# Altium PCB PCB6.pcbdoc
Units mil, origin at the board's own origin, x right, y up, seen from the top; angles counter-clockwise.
Board outline 1190 x 1010 mil, 2 copper layers (Top Layer, Bottom Layer), stack 62.206 mil thick; 18 components, 19 nets, 67 pads, 57 vias.
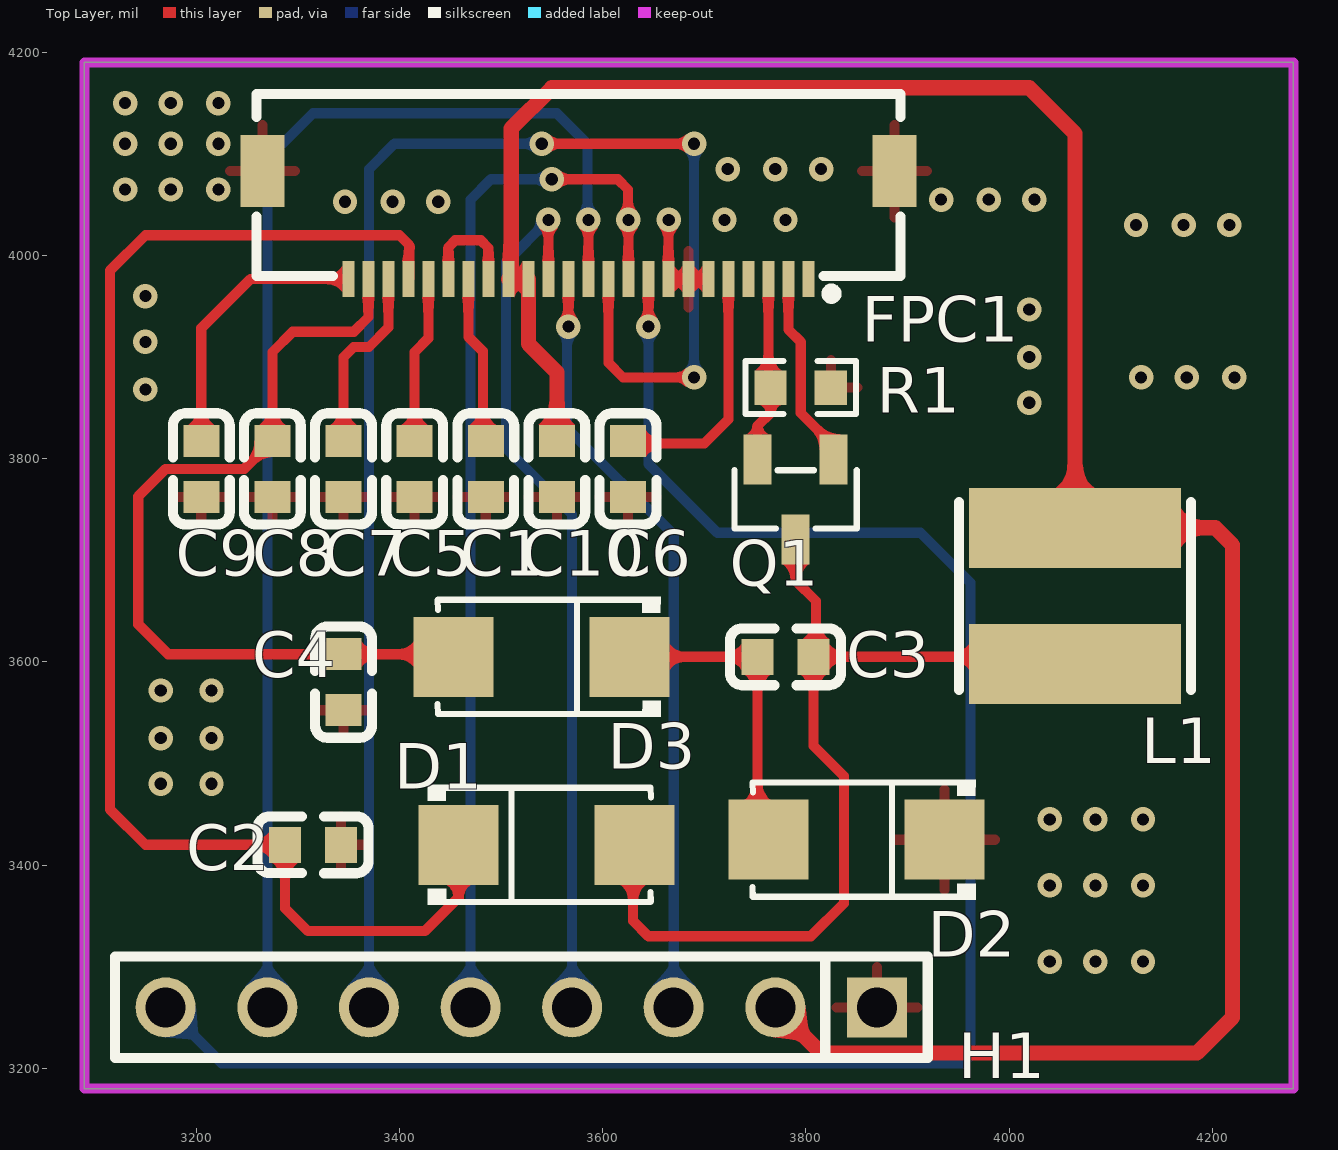
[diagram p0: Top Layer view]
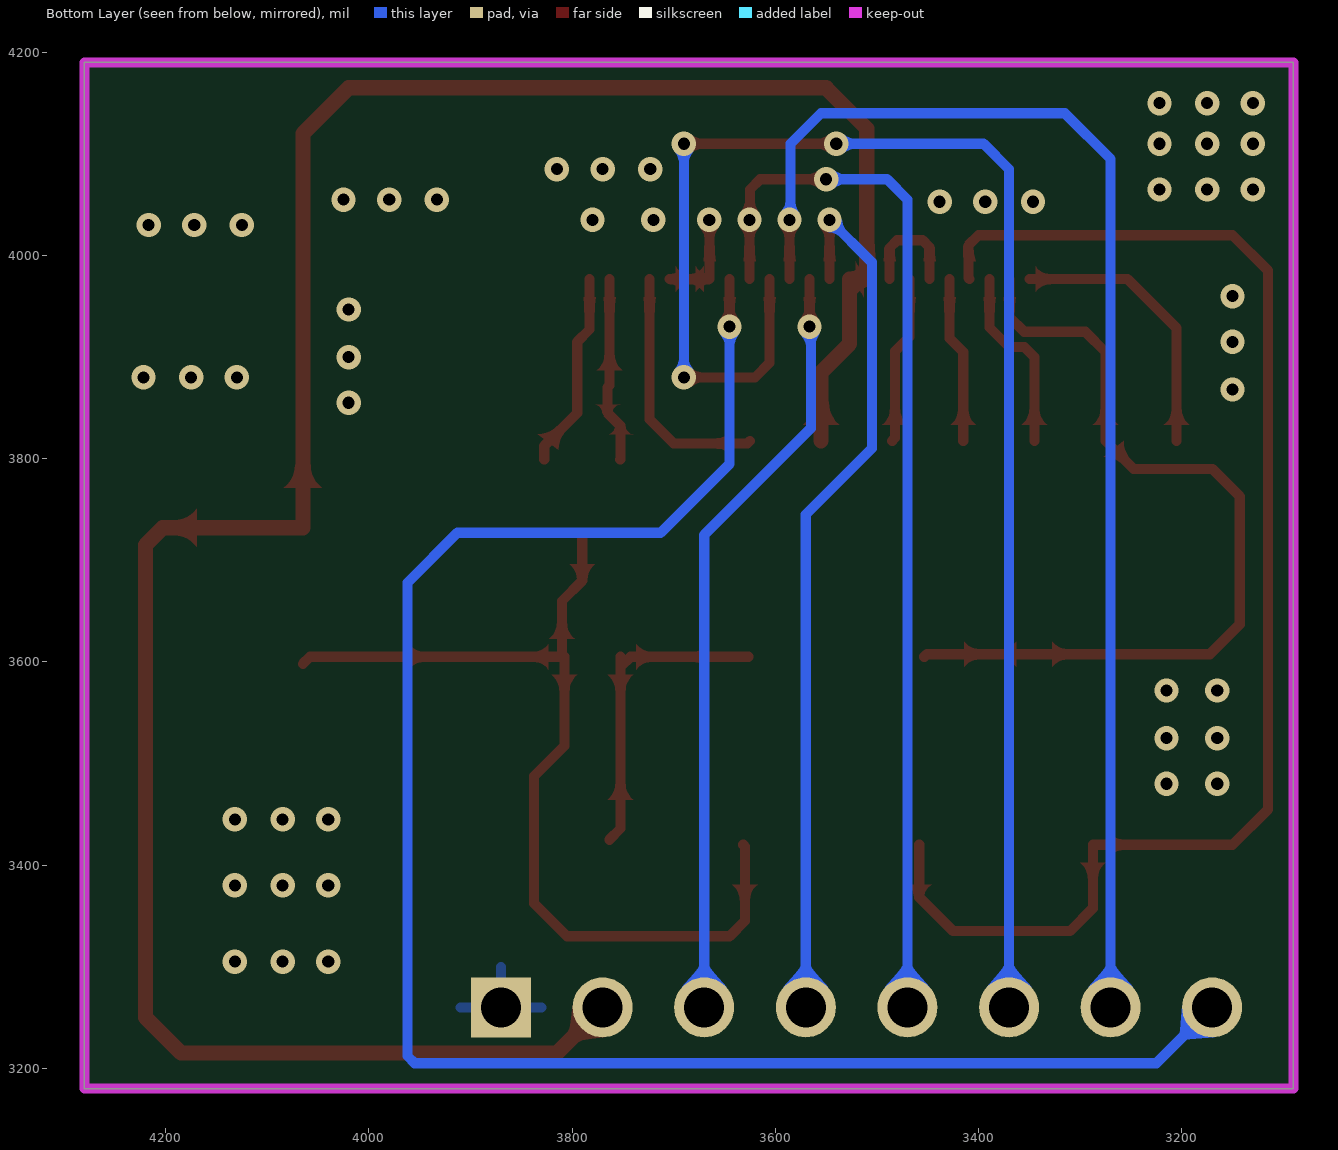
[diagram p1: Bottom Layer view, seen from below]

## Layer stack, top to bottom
Top Solder Mask Layer: solder mask 0.394, Dk 3.3
Top Layer: signal copper 1.379
Dielectric1: surface 59.449, FR4, Dk 4.5
Bottom Layer: signal copper 1.378
Bottom Solder Mask Layer: solder mask 0.394, Dk 3.3

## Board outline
3090,4190 4280,4190 4280,3180 3090,3180

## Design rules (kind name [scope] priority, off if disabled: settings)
BoardOutlineClearance copperThickness1oz [All] p0: genericclearance=10 ignorepadtopadclearanceinfootprint=FALSE except(0: Arc-SplitContinuation Track-SplitContinuation SMDPad-SplitContinuation THPad-SplitContinuation Via-SplitContinuation Fill-SplitContinuation Poly-SplitContinuation Region-SplitContinuation Text-SplitContinuation)
BoardOutlineClearance copperThickness2oz [All] p0: genericclearance=10 ignorepadtopadclearanceinfootprint=FALSE except(0: Arc-SplitContinuation Track-SplitContinuation SMDPad-SplitContinuation THPad-SplitContinuation Via-SplitContinuation Fill-SplitContinuation Poly-SplitContinuation Region-SplitContinuation Text-SplitContinuation)
BoardOutlineClearance otherClearance [All] p0: genericclearance=10 ignorepadtopadclearanceinfootprint=FALSE except(0: Arc-SplitContinuation Track-SplitContinuation SMDPad-SplitContinuation THPad-SplitContinuation Via-SplitContinuation Fill-SplitContinuation Poly-SplitContinuation Region-SplitContinuation Text-SplitContinuation)
Clearance copperThickness1oz [All] p1: gap=7 ignorepadtopadclearanceinfootprint=FALSE
Clearance copperThickness2oz [All] p1: gap=7 ignorepadtopadclearanceinfootprint=FALSE
Clearance otherClearance [All] p1: gap=7 ignorepadtopadclearanceinfootprint=FALSE
DiffPairsRouting differentialPair [All] p1: maxuncoupledlength=10 minlimit=6 maxlimit=Infinity mostfreqgap=6 toplayer_minwidth=5 toplayer_prefwidth=10 toplayer_maxwidth=100 bottomlayer_minwidth=5 bottomlayer_prefwidth=10 bottomlayer_maxwidth=100
PasteMaskExpansion pasteMaskExpansion [All] p1: expansion=0
PlaneConnect innerPlane [All] p1: planeconnectstyle=Relief reliefexpansion=20 reliefentries=4 reliefconductorwidth=10 reliefairgap=10
PolygonConnect copperRegion [All] p1: connectstyle=Relief reliefentries=4 reliefconductorwidth=10 polygonreliefangle="90 Angle" airgapwidth=10
RoutingVias viaSize [All] p1: viastyle="Through Hole" holewidth=12.0078 minholewidth=11.811 maxholewidth=248.0314 width=12.0078 minwidth=11.811 maxwidth=248.0314
SolderMaskExpansion solderMaskExpansion [IsVia] p1: useseparateexpansions=TRUE expansion=-1000 expansionbottom=-1000
SolderMaskExpansion solderMaskExpansion [All] p2: useseparateexpansions=TRUE expansion=2 expansionbottom=2
Width copperThickness1oz [All] p1: maxlimit=100 minlimit=5 preferedwidth=10
Width copperThickness2oz [All] p1: maxlimit=100 minlimit=8 preferedwidth=10

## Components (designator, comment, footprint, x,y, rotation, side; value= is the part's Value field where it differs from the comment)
C1 "1uF" C0603 3485,3790 r90 top
C2 "1uF" C0603 3315,3420 r0 top
C3 "1uF" C0603 3780,3605 r180 top
C4 "1uF" C0603 3345,3580 r270 top
C5 "1uF" C0603 3415,3790 r90 top
C6 "1uF" C0603 3625,3790 r90 top
C7 "1uF" C0603 3345,3790 r90 top
C8 "1uF" C0603 3275,3790 r90 top
C9 "1uF" C0603 3205,3790 r90 top
C10 "1uF" C0603 3555,3790 r90 top
D1 "SS14" SMA_L4.3-W2.6-LS5.2-RD 3545,3420 r0 top
D2 "SS14" SMA_L4.3-W2.6-LS5.2-RD 3850,3425 r180 top
D3 "SS14" SMA_L4.3-W2.6-LS5.2-RD 3540,3605 r180 top
FPC1 "FPC24-T1T1-2021-A" FPC-SMD_FPC24-T1T1-2021-A 3576.18,4029.87 r180 top
H1 "PZ254V-11-08P" HDR-TH_8P-P2.54-V-M 3520,3260 r180 top
L1 "47uH" IND-SMD_L4.7-W4.7_YPRH4D28 4065,3665 r90 top
Q1 "AO3400A" SOT-23-3_L2.9-W1.3-P1.90-LS2.4-BR 3790,3760 r90 top
R1 "2.2Ω" R0603 3795,3870 r180 top

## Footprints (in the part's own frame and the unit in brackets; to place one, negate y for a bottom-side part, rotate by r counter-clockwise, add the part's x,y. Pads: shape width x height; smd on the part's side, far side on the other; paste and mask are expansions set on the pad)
C0603 [mm]
  rect 0.8x0.9 smd: 1(-0.7,0) 2(0.7,0)
  silkscreen extent -1.39,-0.71 1.39,0.71
FPC-SMD_FPC24-T1T1-2021-A [mm]
  rect 0.3x0.9 smd paste+0 mask+0.05: 1(-5.75,1.35) 2(-5.25,1.35) 3(-4.75,1.35) 4(-4.25,1.35) 5(-3.75,1.35) 6(-3.25,1.35) 7(-2.75,1.35) 8(-2.25,1.35) 9(-1.75,1.35) 10(-1.25,1.35) 11(-0.75,1.35) 12(-0.25,1.35) 13(0.25,1.35) 14(0.75,1.35) 15(1.25,1.35) 16(1.75,1.35) 17(2.25,1.35) 18(2.75,1.35) 19(3.25,1.35) 20(3.75,1.35) 21(4.25,1.35) 22(4.75,1.35) 23(5.25,1.35) 24(5.75,1.35)
  rect 1.1x1.8 smd paste+0 mask+0.05: 25(7.9,-1.35) 26(-7.9,-1.35)
  silkscreen extent -8.05,-3.28 8.05,1.84
HDR-TH_8P-P2.54-V-M [mm]
  rect 1.5x1.5 hole 1: 1(-8.89,0)
  round 1.5 hole 1: 2(-6.35,0) 3(-3.81,0) 4(-1.27,0) 5(1.27,0) 6(3.81,0) 7(6.35,0) 8(8.89,0)
  silkscreen extent -10.16,-1.27 10.16,1.27
IND-SMD_L4.7-W4.7_YPRH4D28 [mm]
  rect 2x5.3 smd: 1(-1.7,0) 2(1.7,0)
  silkscreen extent -2.35,-2.9 2.35,2.9
R0603 [mil]
  rect 31.75x34.02 smd paste-3937.01 mask+2: 1(-29.66,0) 2(29.66,0)
  silkscreen extent -55,-26 55,26
SMA_L4.3-W2.6-LS5.2-RD [mm]
  rect 2x2 smd: 1(-2.2,0) 2(2.2,0)
  silkscreen extent -2.98,-1.5 2.6,1.5
SOT-23-3_L2.9-W1.3-P1.90-LS2.4-BR [mm]
  rect 1.25x0.7 smd: 1(1,-0.95) 2(1,0.95) 3(-1,0)
  silkscreen extent -0.73,-1.53 0.73,1.53

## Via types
v1: diameter 24.02, hole 12.01, Top Layer to Bottom Layer, 57 vias

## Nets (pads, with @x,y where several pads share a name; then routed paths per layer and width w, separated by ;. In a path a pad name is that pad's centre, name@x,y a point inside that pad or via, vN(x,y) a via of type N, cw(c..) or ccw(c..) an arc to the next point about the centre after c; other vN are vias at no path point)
$1N32: C3.2 D2.2 D3.1 | length 314.5
  Top Layer w10: D3.1 3742.44,3605 C3.2@3752.44,3595 ; C3.2 C3.2@3752.44,3595 ; D2.2 3752.44,3435.95 C3.2@3752.44,3595
$1N34: C3.1 D1.2 L1.1 Q1.3 | length 943
  Top Layer w10: D1.2 3630,3418.39 3630,3345 3645,3330 3805,3330 3837.5,3362.5 3837.5,3487.5 3807.56,3517.44 C3.1 ; Q1.3 3790,3680 3810,3660 3810,3607.44 C3.1 ; L1.1 4058.07,3605 C3.1
+3V3: C10.2 FPC1.15 FPC1.16 H1.2 L1.2 | length 2428.3
  Top Layer w15: C10.2 3555,3885 3526.97,3913.03 FPC1.15 FPC1.16 3510,3979.44 3510,4125 3550,4165 4020,4165 4065,4120 L1.2 4203.07,3731.93 4220,3715 4220,3250 4185,3215 3815,3215 H1.2
BUSY: FPC1.9 H1.8 | length 1831
  Top Layer w10: v1(3645.08,3930) FPC1.9
  Bottom Layer w10: H1.8 3225,3205 3955,3205 3962.07,3212.07 3962.07,3677.93 3912.93,3727.07 3712.93,3727.07 3645,3795 3645,3929.92 v1(3645.08,3930)
CS: FPC1.12 H1.7 | length 1314.8
  Top Layer w10: FPC1.12 v1(3586.02,4035)
  Bottom Layer w10: H1.7 3270,4095 3315,4140 3555,4140 3585,4110 3585,4036.02 v1(3586.02,4035)
D/C: FPC1.11 H1.6 | length 1558
  Top Layer w10: v1(3540,4110) v1(3690,4110) ; FPC1.11 3605.71,3894.29 3620,3880 v1(3690,3880)
  Bottom Layer w10: H1.6 3370,4085 3395,4110 v1(3540,4110) ; v1(3690,3880) v1(3690,4110)
GDR: FPC1.2 Q1.1 | length 195.8
  Top Layer w10: FPC1.2 3782.87,3927.13 3795,3915 3795,3845 3827.4,3812.6 Q1.1
GND: C1.1 C2.2 C4.2 C5.1 C6.1 C7.1 C8.1 C9.1 C10.1 D2.1 FPC1.6 FPC1.7 FPC1.8 FPC1.17 FPC1.19 FPC1.25 FPC1.26 H1.1 R1.1 | length 205.3
  Top Layer w10: FPC1.19 3448.23,4008.23 3455,4015 3480,4015 3487.6,4007.4 FPC1.17 ; v1(3665,4035) 3664.76,4034.76 FPC1.8 FPC1.7 FPC1.6
  other v1: 4040,3305 4085,3305 4131.88,3305 4040,3380 4085,3380 4131.88,3380 4040,3445 4085,3445 4131.88,3445 3165,3480 3215,3480 3165,3525 3215,3525 3165,3571.88 3215,3571.88 4020,3855 3150,3868.12 4130,3880 4175,3880 4221.88,3880 4020,3900 3150,3915 4020,3946.88 3150,3960 4125,4030 4171.88,4030 4216.88,4030 3720,4035 3780,4035 3346.43,4052.95 3393.31,4052.95 3438.31,4052.95 3933.12,4055 3980,4055 4025,4055 3130,4065 3175,4065 3221.88,4065 3723.12,4085 3770,4085 3815,4085 3130,4110 3175,4110 3221.88,4110 3130,4150 3175,4150 3221.88,4150
RES: FPC1.10 H1.5 | length 1050.9
  Top Layer w10: v1(3550,4075) 3615,4075 3625,4065 3625,4035.39 v1(3625.39,4035) FPC1.10
  Bottom Layer w10: H1.5 3470,4055 3490,4075 v1(3550,4075)
RESE: FPC1.3 Q1.2 R1.2 | length 183.6
  Top Layer w10: Q1.2 3752.5,3799.47 3752.5,3832.5 3765.34,3845.34 R1.2 3763.19,3872.15 FPC1.3
SCL: FPC1.13 H1.3 | length 760.8
  Top Layer w10: v1(3566.34,3930) FPC1.13
  Bottom Layer w10: v1(3566.34,3930) 3565,3928.66 3565,3830 3670,3725 H1.3
SDA: FPC1.14 H1.4 | length 877.5
  Top Layer w10: FPC1.14 v1(3546.65,4035)
  Bottom Layer w10: v1(3546.65,4035) 3505,3993.35 3505,3810 3570,3745 H1.4
VCOM: C9.2 FPC1.24 | length 275.7
  Top Layer w10: C9.2 3205,3928.45 3253.28,3976.72 FPC1.24
VDD: C1.2 FPC1.18 | length 166.2
  Top Layer w10: FPC1.18 3467.91,3920 3482.18,3905.73 3482.18,3820.38 C1.2
VGH: C2.1 D1.1 FPC1.21 | length 1372.5
  Top Layer w10: FPC1.21 3410,3977.86 3410,4010 3400,4020 3150,4020 3115,3985 3115,3455 3150,3420 C2.1 3287.44,3357.56 3310,3335 3425,3335 3458.39,3368.39 D1.1
VGL: C4.1 C8.2 D3.2 FPC1.23 | length 837.8
  Top Layer w10: FPC1.23 3369.49,3939.49 3355,3925 3295,3925 3275,3905 C8.2 3247.44,3790 3170,3790 3142.93,3762.93 3142.93,3637.07 3172.44,3607.56 C4.1 3450.83,3607.56 D3.2
VSH1: C5.2 FPC1.20 | length 164.8
  Top Layer w10: C5.2 3415,3905 3428.54,3918.54 FPC1.20
VSH2: C6.2 FPC1.5 | length 247.7
  Top Layer w10: C6.2 3627.56,3815 3700,3815 3723.82,3838.82 FPC1.5
VSL: C7.2 FPC1.22 | length 186.2
  Top Layer w10: C7.2 3345,3900 3355,3910 3370,3910 3389.17,3929.17 FPC1.22
pads on no net: FPC1.1 FPC1.4

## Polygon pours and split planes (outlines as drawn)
GND on Top Layer (solid, remove dead copper, pour order 0): 3045,4245 4380,4245 4380,3065 3045,3065
GND on Bottom Layer (solid, remove dead copper, pour order 4): 3000,4305 4490,4305 4490,3000 3000,3000

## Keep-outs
Board Outline Layer:
  the board outline again, w10

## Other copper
Top Layer:
  region net VCOM: 3328.9,3971.72 3328.9,3981.72 ccw(c3328.9,4000.47) 3343.9,3989.22 3343.9,3964.22 ccw(c3328.9,3952.97)
  region net VCOM: 3200,3848.31 3210,3848.31 ccw(c3228.75,3848.31) 3217.5,3833.31 3192.5,3833.31 ccw(c3181.25,3848.31)
  region net VSL: 3394.17,3944.01 3384.17,3944.01 ccw(c3259.48,3944.01) 3383.27,3959.01 3395.08,3959.01 ccw(c3518.87,3944.01)
  region net VSL: 3340,3848.31 3350,3848.31 ccw(c3368.75,3848.31) 3357.5,3833.31 3332.5,3833.31 ccw(c3321.25,3848.31)
  region net VSH1: 3433.54,3944.01 3423.54,3944.01 ccw(c3298.85,3944.01) 3422.64,3959.01 3434.45,3959.01 ccw(c3558.24,3944.01)
  region net VSH1: 3410,3848.31 3420,3848.31 ccw(c3438.75,3848.31) 3427.5,3833.31 3402.5,3833.31 ccw(c3391.25,3848.31)
  region net VGL: 3270,3848.31 3280,3848.31 ccw(c3298.75,3848.31) 3287.5,3833.31 3262.5,3833.31 ccw(c3251.25,3848.31)
  region net VGL: 3374.49,3944.01 3364.49,3944.01 ccw(c3239.8,3944.01) 3363.59,3959.01 3375.4,3959.01 ccw(c3499.19,3944.01)
  region net VDD: 3472.91,3944.01 3462.91,3944.01 ccw(c3338.22,3944.01) 3462.01,3959.01 3473.82,3959.01 ccw(c3597.61,3944.01)
  region net VDD: 3477.18,3848.31 3487.18,3848.31 ccw(c3505.93,3848.31) 3494.68,3833.31 3469.68,3833.31 ccw(c3458.43,3848.31)
  region net RESE: 3768.19,3944.01 3758.19,3944.01 ccw(c3633.5,3944.01) 3757.29,3959.01 3769.1,3959.01 ccw(c3892.89,3944.01)
  region net RESE: 3758.19,3902.01 3768.19,3902.01 ccw(c3786.94,3902.01) 3775.69,3887.01 3750.69,3887.01 ccw(c3739.44,3902.01)
  region net RESE: 3770.34,3845.34 3760.34,3845.34 ccw(c3752.69,3845.34) 3752.84,3852.99 3777.84,3852.99 ccw(c3777.99,3845.34)
  region net RESE: 3747.5,3832.5 3757.5,3832.5 ccw(c3766.09,3832.5) 3765,3823.98 3740,3823.98 ccw(c3738.91,3832.5)
  region net GDR: 3787.87,3944.01 3777.87,3944.01 ccw(c3653.18,3944.01) 3776.97,3959.01 3788.78,3959.01 ccw(c3912.57,3944.01)
  region net GDR: 3808.32,3824.61 3817.79,3829.28 ccw(c3833.7,3850.49) 3833.7,3823.98 3813.62,3808.7 ccw(c3787.1,3808.7)
  region net $1N32: 3680.98,3610 3680.98,3600 ccw(c3680.98,3581.25) 3665.98,3592.5 3665.98,3617.5 ccw(c3680.98,3628.75)
  region net $1N32: 3721.69,3600 3721.69,3610 ccw(c3721.69,3628.75) 3736.69,3617.5 3736.69,3592.5 ccw(c3721.69,3581.25)
  region net $1N34: 3838.31,3610 3838.31,3600 ccw(c3838.31,3581.25) 3823.31,3592.5 3823.31,3617.5 ccw(c3838.31,3628.75)
  region net $1N34: 3945.67,3600 3945.67,3610 ccw(c3945.67,3628.75) 3960.67,3617.5 3960.67,3592.5 ccw(c3945.67,3581.25)
  region net $1N34: 3795,3681.02 3785,3681.02 ccw(c3766.25,3681.02) 3777.5,3696.02 3802.5,3696.02 ccw(c3813.75,3681.02)
  region net $1N34: 3805,3637.72 3815,3637.72 ccw(c3833.75,3637.72) 3822.5,3622.72 3797.5,3622.72 ccw(c3786.25,3637.72)
  region net $1N32: 3757.44,3572.28 3747.44,3572.28 ccw(c3728.69,3572.28) 3739.94,3587.28 3764.94,3587.28 ccw(c3776.19,3572.28)
  region net $1N32: 3747.44,3479.37 3757.44,3479.37 ccw(c3776.19,3479.37) 3764.94,3464.37 3739.94,3464.37 ccw(c3728.69,3479.37)
  region net $1N34: 3812.56,3572.28 3802.56,3572.28 ccw(c3783.81,3572.28) 3795.06,3587.28 3820.06,3587.28 ccw(c3831.31,3572.28)
  region net $1N34: 3635,3365.63 3625,3365.63 ccw(c3606.25,3365.63) 3617.5,3380.63 3642.5,3380.63 ccw(c3653.75,3365.63)
  region net VGL: 3261.02,3796.51 3251.98,3801.61 ccw(c3230.77,3817.52) 3257.28,3817.52 3276.93,3801.81 ccw(c3276.93,3775.3)
  region net VGL: 3312.28,3602.56 3312.28,3612.56 ccw(c3312.28,3631.31) 3327.28,3620.06 3327.28,3595.06 ccw(c3312.28,3583.81)
  region net VGL: 3377.72,3612.56 3377.72,3602.56 ccw(c3377.72,3583.81) 3362.72,3595.06 3362.72,3620.06 ccw(c3377.72,3631.31)
  region net VGL: 3399.02,3602.56 3399.02,3612.56 ccw(c3399.02,3631.31) 3414.02,3620.06 3414.02,3595.06 ccw(c3399.02,3583.81)
  region net VGH: 3292.44,3387.28 3282.44,3387.28 ccw(c3263.69,3387.28) 3274.94,3402.28 3299.94,3402.28 ccw(c3311.19,3387.28)
  region net VGH: 3463.39,3368.39 3453.39,3368.39 ccw(c3439.65,3368.39) 3445.89,3380.63 3470.89,3380.63 ccw(c3477.13,3368.39)
  region net VGH: 3256.69,3415 3256.69,3425 ccw(c3256.69,3443.75) 3271.69,3432.5 3271.69,3407.5 ccw(c3256.69,3396.25)
  region net VGH: 3405,4009.44 3415,4009.44 ccw(c3898.76,3994.44) 3414.77,3994.44 3402.96,3994.44 ccw(c3348.93,4009.44)
  region net +3V3: 3547.5,3855.81 3562.5,3855.81 ccw(c3592.38,3855.81) 3572.72,3833.31 3537.28,3833.31 ccw(c3517.62,3855.81)
  region net +3V3: 3526.97,3984.22 3526.97,3969.22 ccw(c3526.97,3954.82) 3513.19,3959.01 3513.19,3994.44 ccw(c3526.97,3998.63)
  region net +3V3: 3507.28,3969.22 3507.28,3984.22 ccw(c3507.28,3998.63) 3521.07,3994.44 3521.07,3959.01 ccw(c3507.28,3954.82)
  region net VSH2: 3728.82,3944.01 3718.82,3944.01 ccw(c3594.13,3944.01) 3717.92,3959.01 3729.73,3959.01 ccw(c3853.52,3944.01)
  region net VSH2: 3657.72,3820 3657.72,3810 ccw(c3657.72,3791.25) 3642.72,3802.5 3642.72,3827.5 ccw(c3657.72,3838.75)
  region net SDA: 3541.65,4009.44 3551.65,4009.44 ccw(c3676.35,4009.44) 3552.56,3994.44 3540.75,3994.44 ccw(c3416.96,4009.44)
  region net SDA: 3551.65,4018.65 3541.65,4018.65 3541.31,4020.46 3540.4,4022.73 3539.12,4025.06 3537.65,4027.06 3555.66,4027.06 3554.19,4025.06 3552.9,4022.73 3552,4020.46
  region net SCL: 3571.34,3944.01 3561.34,3944.01 ccw(c3436.65,3944.01) 3560.44,3959.01 3572.25,3959.01 ccw(c3696.04,3944.01)
  region net SCL: 3561.34,3946.35 3571.34,3946.35 3571.69,3944.54 3572.59,3942.27 3573.88,3939.94 3575.35,3937.94 3557.34,3937.94 3558.81,3939.94 3560.09,3942.27 3561,3944.54
  region net CS: 3581.02,4009.44 3591.02,4009.44 ccw(c3715.72,4009.44) 3591.93,3994.44 3580.12,3994.44 ccw(c3456.33,4009.44)
  region net CS: 3591.02,4018.65 3581.02,4018.65 3580.68,4020.46 3579.77,4022.73 3578.49,4025.06 3577.02,4027.06 3595.03,4027.06 3593.56,4025.06 3592.27,4022.73 3591.37,4020.46
  region net RES: 3620.39,4009.44 3630.39,4009.44 ccw(c3755.09,4009.44) 3631.3,3994.44 3619.49,3994.44 ccw(c3495.7,4009.44)
  region net RES: 3630.39,4018.65 3620.39,4018.65 3620.05,4020.46 3619.14,4022.73 3617.86,4025.06 3616.39,4027.06 3634.4,4027.06 3632.93,4025.06 3631.64,4022.73 3630.74,4020.46
  region net BUSY: 3650.08,3944.01 3640.08,3944.01 ccw(c3515.39,3944.01) 3639.18,3959.01 3650.99,3959.01 ccw(c3774.78,3944.01)
  region net BUSY: 3640.08,3946.35 3650.08,3946.35 3650.43,3944.54 3651.33,3942.27 3652.62,3939.94 3654.09,3937.94 3636.08,3937.94 3637.55,3939.94 3638.83,3942.27 3639.74,3944.54
  region net +3V3: 4057.5,3793.8 4072.5,3793.8 ccw(c4100.62,3793.8) 4083.75,3771.3 4046.25,3771.3 ccw(c4029.38,3793.8)
  region net +3V3: 3502.5,4016.94 3517.5,4016.94 ccw(c3574.04,3994.44) 3513.19,3994.44 3501.38,3994.44 ccw(c3276.64,4016.94)
  region net +3V3: 3803.73,3236.88 3793.12,3226.27 3792.09,3226.84 3790.17,3227.45 3784.24,3228.68 3776.51,3229.77 3768.15,3230.53 3799.47,3261.85 3800.23,3253.49 3801.32,3245.76 3802.55,3239.83 3803.16,3237.91
  region net +3V3: 4191.83,3739.43 4191.83,3724.43 ccw(c4191.83,3696.3) 4169.33,3713.18 4169.33,3750.68 ccw(c4191.83,3767.55)
  region net RES: 3566.35,4080 3566.35,4070 3564.54,4069.66 3562.27,4068.75 3559.94,4067.47 3557.94,4065.99 3557.94,4084.01 3559.94,4082.53 3562.27,4081.25 3564.54,4080.34
  region net RES: 3620,4051.05 3630,4051.64 3630.36,4049.79 3631.29,4047.51 3632.62,4045.19 3634.13,4043.23 3616.13,4042.64 3617.55,4044.68 3618.79,4047.03 3619.67,4049.28
  region net D/C: 3610.71,3944.01 3600.71,3944.01 ccw(c3476.02,3944.01) 3599.81,3959.01 3611.62,3959.01 ccw(c3735.41,3944.01)
  region net D/C: 3673.65,3875 3673.65,3885 3675.46,3885.34 3677.73,3886.25 3680.06,3887.53 3682.06,3889.01 3682.06,3870.99 3680.06,3872.47 3677.73,3873.75 3675.46,3874.66
  region net D/C: 3556.35,4115 3556.35,4105 3554.54,4104.66 3552.27,4103.75 3549.94,4102.47 3547.94,4100.99 3547.94,4119.01 3549.94,4117.53 3552.27,4116.25 3554.54,4115.34
  region net D/C: 3673.65,4105 3673.65,4115 3675.46,4115.34 3677.73,4116.25 3680.06,4117.53 3682.06,4119.01 3682.06,4100.99 3680.06,4102.47 3677.73,4103.75 3675.46,4104.66
  region net GND: 3659.76,4009.44 3669.76,4009.44 ccw(c3794.46,4009.44) 3670.67,3994.44 3658.86,3994.44 ccw(c3535.07,4009.44)
  region net GND: 3669.76,4018.48 3659.76,4018.83 3659.42,4020.62 3658.54,4022.87 3657.28,4025.21 3655.84,4027.24 3673.85,4026.88 3672.35,4024.91 3671.04,4022.58 3670.11,4020.31
  region net GND: 3664.76,3971.72 3664.76,3981.72 ccw(c3664.76,3998.14) 3678.55,3989.22 3678.55,3964.22 ccw(c3664.76,3955.3)
  region net GND: 3684.45,3981.72 3684.45,3971.72 ccw(c3684.45,3955.3) 3670.67,3964.22 3670.67,3989.22 ccw(c3684.45,3998.14)
  region net GND: 3704.13,3981.72 3704.13,3971.72 ccw(c3704.13,3955.32) 3690.36,3964.22 3690.36,3989.22 ccw(c3704.13,3998.12)
  region net GND: 3684.45,3971.72 3684.45,3981.72 ccw(c3684.45,3998.12) 3698.23,3989.22 3698.23,3964.22 ccw(c3684.45,3955.32)
  region net GND: 3482.6,4007.4 3492.6,4007.4 ccw(c3585.79,4007.4) 3493.51,3994.44 3481.7,3994.44 ccw(c3389.42,4007.4)
  region net GND: 3443.23,4008.23 3453.23,4008.23 ccw(c3558.74,4008.23) 3454.14,3994.44 3442.33,3994.44 ccw(c3337.73,4008.23)
Bottom Layer:
  region net CS: 3265,3300.2 3275,3300.2 3276.47,3298.08 3280.36,3293.28 3292.15,3279.53 3247.85,3279.53 3259.64,3293.28 3263.53,3298.08
  region net CS: 3580,4050.55 3590,4052.09 3590.1,4051.2 3590.37,4050.16 3591.35,4047.86 3592.73,4045.56 3594.32,4043.68 3576.37,4042.15 3577.7,4044.25 3578.87,4046.61 3579.69,4048.84
  region net SDA: 3565,3300.2 3575,3300.2 3576.47,3298.08 3580.36,3293.28 3592.15,3279.53 3547.85,3279.53 3559.64,3293.28 3563.53,3298.08
  region net SDA: 3538.63,4019.9 3531.56,4026.98 3532.59,4028.5 3533.55,4030.74 3534.29,4033.3 3534.67,4035.75 3547.4,4023.02 3544.95,4022.64 3542.39,4021.9 3540.15,4020.94
  region net SCL: 3570,3912.7 3560,3914.71 3559.7,3916.39 3558.91,3918.61 3557.79,3920.99 3556.5,3923.11 3574.4,3921.1 3572.79,3919.26 3571.38,3916.98 3570.38,3914.66 3570.1,3913.61
  region net SCL: 3665,3300.2 3675,3300.2 3676.47,3298.08 3680.36,3293.28 3692.15,3279.53 3647.85,3279.53 3659.64,3293.28 3663.53,3298.08
  region net RES: 3465,3300.2 3475,3300.2 3476.47,3298.08 3480.36,3293.28 3492.15,3279.53 3447.85,3279.53 3459.64,3293.28 3463.53,3298.08
  region net RES: 3533.65,4070 3533.65,4080 3535.46,4080.34 3537.73,4081.25 3540.06,4082.53 3542.06,4084.01 3542.06,4065.99 3540.06,4067.47 3537.73,4068.75 3535.46,4069.66
  region net D/C: 3365,3300.2 3375,3300.2 3376.47,3298.08 3380.36,3293.28 3392.15,3279.53 3347.85,3279.53 3359.64,3293.28 3363.53,3298.08
  region net D/C: 3523.65,4105 3523.65,4115 3525.46,4115.34 3527.73,4116.25 3530.06,4117.53 3532.06,4119.01 3532.06,4100.99 3530.06,4102.47 3527.73,4103.75 3525.46,4104.66
  region net BUSY: 3201.96,3235.11 3194.89,3228.04 3192.35,3228.5 3186.21,3229.14 3168.15,3230.53 3199.47,3261.85 3200.86,3243.79 3201.5,3237.65
  region net BUSY: 3650,3913.59 3640,3913.71 3639.66,3915.51 3638.76,3917.78 3637.48,3920.11 3636.02,3922.12 3654.03,3922 3652.55,3920.01 3651.26,3917.68 3650.35,3915.41
  region net D/C: 3695,4093.65 3685,4093.65 3684.66,4095.46 3683.75,4097.73 3682.47,4100.06 3680.99,4102.06 3699.01,4102.06 3697.53,4100.06 3696.25,4097.73 3695.34,4095.46
  region net D/C: 3685,3896.35 3695,3896.35 3695.34,3894.54 3696.25,3892.27 3697.53,3889.94 3699.01,3887.94 3680.99,3887.94 3682.47,3889.94 3683.75,3892.27 3684.66,3894.54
